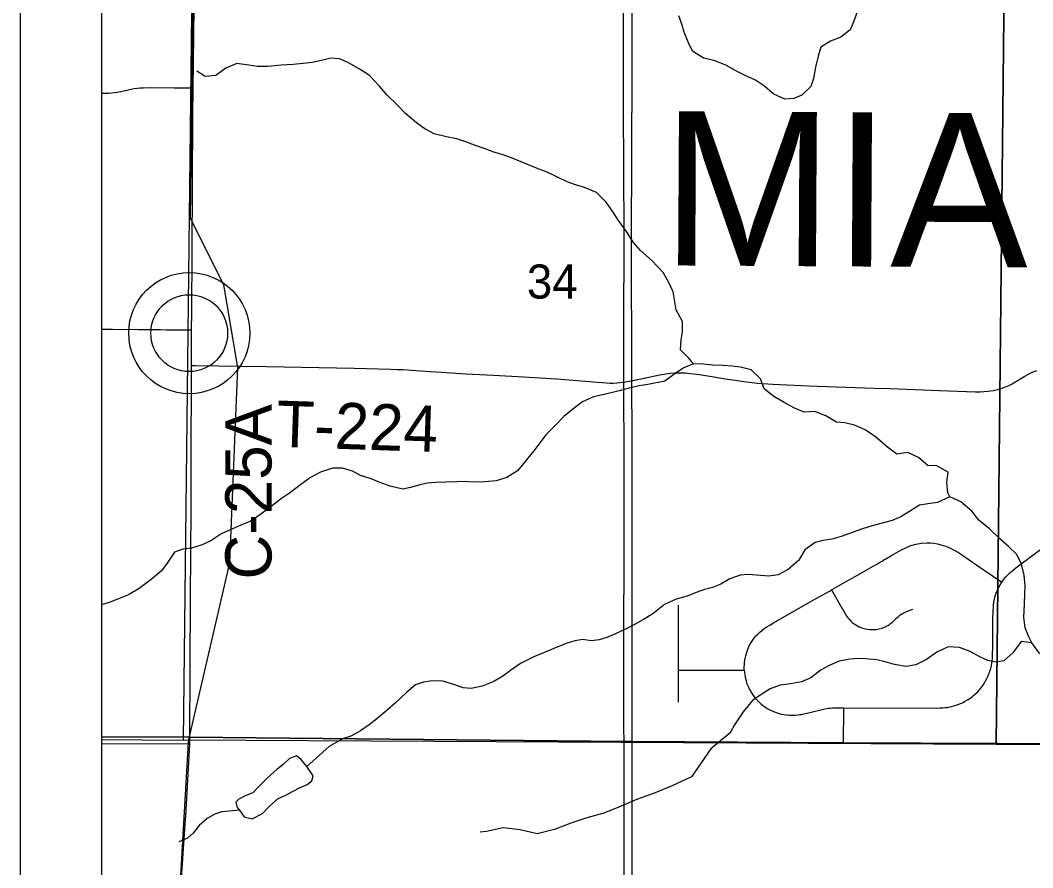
# Model space of a CAD drawing. Extents: x -38.1 to 35.9, y -2.7 to 28.5.
# Drawn here: x 8.015 to 9.259, y 17.716 to 18.757 of the extents above; entities that cross this region are included whole.
import ezdxf

# ---------------------------------------------------------------- set-up
doc = ezdxf.new("R2010")
doc.units = 0
for name, color, linetype in [('GM_X_City_Street_Text', 7, 'Continuous'), ('GM_X_Corporation', 7, 'Continuous'), ('GM_X_Corporation_Text', 7, 'Continuous'), ('GM_X_County_ROW', 7, 'Continuous'), ('GM_X_Major_River_Text', 7, 'Continuous'), ('GM_X_Minor_Lake', 7, 'Continuous'), ('GM_X_Minor_River', 7, 'Continuous'), ('GM_X_Rail_Line', 7, 'Continuous'), ('GM_X_Section', 7, 'Continuous'), ('GM_X_State_Location', 7, 'Continuous'), ('GM_X_Township', 7, 'Continuous'), ('GM_X_US_Route', 7, 'Continuous'), ('SC_Scratch10', 7, 'Continuous'), ('SH_Border', 7, 'Continuous'), ('SH_Data', 7, 'Continuous')]:
    doc.layers.add(name, color=color, linetype=linetype)

msp = doc.modelspace()

# ---------------------------------------------------------------- linework, layer by layer
at = {"layer": 'GM_X_City_Street_Text'}
for p, q in [((8.225, 18.3326), (8.2252, 18.3763)), ((8.1146, 17.8683), (8.2231, 17.868))]:
    msp.add_line(p, q, dxfattribs=at)
for points in [[(8.2272, 18.674), (8.2276, 18.704), (8.2294, 18.8765)], [(8.2252, 18.3763), (8.2253, 18.3982), (8.2257, 18.4727), (8.2268, 18.6384), (8.2272, 18.674)], [(8.1146, 18.3774), (8.128, 18.3772), (8.1597, 18.377), (8.1684, 18.3769), (8.1746, 18.3769), (8.187, 18.3767), (8.1944, 18.3766), (8.2062, 18.3765), (8.2174, 18.3764), (8.2252, 18.3763)], [(8.2231, 17.8756), (8.224, 18.0471), (8.2245, 18.157), (8.2246, 18.1724), (8.2246, 18.1898), (8.2246, 18.1954), (8.2245, 18.2077), (8.225, 18.3326)], [(8.1677, 16.8817), (8.1695, 16.9932), (8.1765, 17.1126), (8.1815, 17.1762), (8.1988, 17.4691), (8.2052, 17.587), (8.2104, 17.6664), (8.2151, 17.7391), (8.2187, 17.7863), (8.2231, 17.868), (8.2231, 17.8756)]]:
    msp.add_lwpolyline(points, dxfattribs=at)
at = {"layer": 'GM_X_Corporation'}
for points in [[(8.2224, 17.8749), (8.2723, 18.0901), (8.2822, 18.3302), (8.2647, 18.4319), (8.2238, 18.5131), (8.2346, 19.3814), (8.3741, 19.3825), (8.9096, 19.7308)], [(8.1169, 12.9308), (8.1202, 13.4509), (8.1267, 14.3761), (8.1272, 14.5808), (8.1295, 14.9033), (8.1448, 15.2944), (8.1561, 15.4105), (8.2031, 15.8872), (8.1758, 16.5559), (8.1657, 16.8852), (8.1819, 17.1843), (8.2212, 17.8697), (8.2224, 17.8749)]]:
    msp.add_lwpolyline(points, dxfattribs=at)
at = {"layer": 'GM_X_Corporation_Text'}
for points in [[(8.7566, 17.8702), (8.7564, 17.8882), (8.7566, 18.2138), (8.7564, 18.3123), (8.7563, 18.3729), (8.7565, 18.4952), (8.756, 18.6507), (8.756, 18.8701), (8.756, 18.8775), (8.756, 19.0727), (8.756, 19.2616), (8.7561, 19.3813), (8.7561, 19.3828), (8.7556, 19.4318), (8.7555, 19.4834), (8.7557, 19.6068), (8.7558, 19.7308)], [(8.7664, 17.8701), (8.7666, 18.0138), (8.7665, 18.2438), (8.7663, 18.314), (8.7659, 18.4879), (8.7665, 18.6953), (8.7665, 18.8603), (8.7664, 18.8775), (8.7659, 19.0196), (8.7659, 19.2772), (8.7659, 19.3825), (8.7659, 19.3835)], [(8.7584, 16.4935), (8.7576, 16.6966), (8.7571, 16.8386), (8.7573, 16.969), (8.7576, 17.0093), (8.7576, 17.0139), (8.7575, 17.1756), (8.7573, 17.3174), (8.7571, 17.4714), (8.7571, 17.6068), (8.7568, 17.6716), (8.7567, 17.7848), (8.7566, 17.8702)], [(8.767, 16.8813), (8.7671, 16.9689), (8.7674, 17.0079), (8.7675, 17.0138), (8.7673, 17.1755), (8.7671, 17.3173), (8.767, 17.4713), (8.767, 17.6067), (8.7666, 17.6715), (8.7665, 17.7847), (8.7664, 17.8701)]]:
    msp.add_lwpolyline(points, dxfattribs=at)
at = {"layer": 'GM_X_County_ROW'}
msp.add_line((8.2223, 18.3724), (8.2223, 18.3724), dxfattribs=at)
at = {"layer": 'GM_X_Major_River_Text'}
for p, q in [((8.8236, 17.9583), (8.8235, 18.0383)), ((8.8234, 17.919), (8.8236, 17.9583)), ((8.8236, 17.9583), (8.9042, 17.9585)), ((9.0264, 17.8684), (9.0268, 17.912))]:
    msp.add_line(p, q, dxfattribs=at)
for points in [[(8.1146, 18.6674), (8.1185, 18.6673), (8.123, 18.6674), (8.1267, 18.6677), (8.1305, 18.668), (8.1342, 18.6685), (8.1379, 18.6692), (8.1414, 18.6701), (8.1457, 18.6711), (8.1511, 18.6723), (8.1545, 18.6729), (8.1585, 18.6734), (8.1621, 18.6738), (8.1659, 18.674), (8.1759, 18.6742), (8.2038, 18.6739), (8.2181, 18.674), (8.2272, 18.674)], [(8.225, 18.3326), (8.2297, 18.3325), (8.2859, 18.3317), (8.3172, 18.3313), (8.4248, 18.3292), (8.47, 18.3282), (8.4778, 18.3279), (8.4842, 18.3276), (8.5065, 18.3262), (8.532, 18.3244), (8.5622, 18.3225), (8.5878, 18.3211), (8.6037, 18.3203), (8.6261, 18.3191), (8.674, 18.3162), (8.7239, 18.3121), (8.7299, 18.3117), (8.7346, 18.3113), (8.7396, 18.311), (8.7431, 18.3109), (8.7478, 18.3112), (8.7552, 18.3121), (8.7564, 18.3123), (8.7604, 18.3129), (8.7663, 18.314), (8.7675, 18.3143), (8.7832, 18.3175), (8.8001, 18.321), (8.8132, 18.3232), (8.8195, 18.3237), (8.8242, 18.3238), (8.828, 18.3237), (8.8319, 18.3235), (8.8379, 18.3229), (8.8421, 18.3224), (8.8492, 18.3215), (8.8669, 18.3186), (8.8809, 18.3163), (8.8901, 18.3149), (8.9036, 18.3129), (8.9207, 18.3111), (8.9392, 18.3096), (8.9662, 18.3083), (8.9739, 18.308), (8.9937, 18.3074), (9.0526, 18.3051), (9.0638, 18.3048), (9.0837, 18.3043), (9.144, 18.3021), (9.1885, 18.3005), (9.1942, 18.3005), (9.1988, 18.3007), (9.2035, 18.301), (9.2069, 18.3014), (9.2106, 18.302), (9.2175, 18.3036), (9.2244, 18.3059), (9.2287, 18.3078), (9.2334, 18.3102), (9.2388, 18.3134), (9.2491, 18.3197), (9.2536, 18.3221), (9.2571, 18.3239), (9.2636, 18.3265)], [(9.2206, 18.0666), (9.2237, 18.0706), (9.2258, 18.073), (9.228, 18.0754), (9.2307, 18.078), (9.2346, 18.0814), (9.2378, 18.0839), (9.2413, 18.0866), (9.2731, 18.1101), (9.31, 18.1378), (9.3336, 18.1555), (9.3401, 18.1603), (9.3455, 18.1645)], [(9.0115, 18.057), (9.0286, 18.0667), (9.0405, 18.0735), (9.054, 18.0811), (9.0626, 18.086), (9.0679, 18.0891), (9.0715, 18.0914), (9.0737, 18.0924), (9.0757, 18.0937), (9.0783, 18.0952), (9.0831, 18.098), (9.0857, 18.0996), (9.0879, 18.1008), (9.0936, 18.1042), (9.0982, 18.1066), (9.101, 18.108), (9.1044, 18.1096), (9.1051, 18.1099), (9.1091, 18.1114), (9.1107, 18.1119), (9.1152, 18.1131), (9.1221, 18.1143), (9.1286, 18.1147), (9.133, 18.1146), (9.1372, 18.1143), (9.1417, 18.1135), (9.1458, 18.1125), (9.1506, 18.1111), (9.1529, 18.1103), (9.1577, 18.1082), (9.1606, 18.1067), (9.1638, 18.1049), (9.1676, 18.1027), (9.1713, 18.1003), (9.1902, 18.0874), (9.2206, 18.0666)], [(9.0268, 17.912), (9.1399, 17.9117), (9.1447, 17.9119), (9.1482, 17.9121), (9.151, 17.9123), (9.1536, 17.9126), (9.155, 17.9128), (9.1568, 17.9132), (9.1594, 17.9138), (9.1615, 17.9144), (9.1647, 17.9154), (9.1678, 17.9164), (9.1712, 17.9177), (9.1733, 17.9187), (9.175, 17.9197), (9.1792, 17.9221), (9.1816, 17.9237), (9.1846, 17.926), (9.1869, 17.9279), (9.1895, 17.9303), (9.1911, 17.9318), (9.1928, 17.9339), (9.195, 17.9364), (9.1973, 17.9396), (9.1989, 17.942), (9.2008, 17.9452), (9.2023, 17.948), (9.2038, 17.9513), (9.2048, 17.9538), (9.206, 17.9569), (9.2071, 17.9603), (9.208, 17.9639), (9.2085, 17.9665), (9.2089, 17.9695), (9.2092, 17.9725), (9.2094, 17.9767), (9.2098, 17.988), (9.2099, 18.0197), (9.2102, 18.0309), (9.2105, 18.0365), (9.2107, 18.0395), (9.2109, 18.0407), (9.2111, 18.0427), (9.2113, 18.0439), (9.2116, 18.0456), (9.2122, 18.0477), (9.2127, 18.0496), (9.2134, 18.0516), (9.2143, 18.0541), (9.2154, 18.0567), (9.2168, 18.0596), (9.2186, 18.0631), (9.2206, 18.0666)], [(8.9042, 17.9585), (8.9043, 17.962), (8.9044, 17.9658), (8.9045, 17.9673), (8.905, 17.9709), (8.906, 17.9758), (8.9077, 17.9817), (8.9094, 17.9862), (8.9112, 17.99), (8.9135, 17.9937), (8.9151, 17.996), (8.9178, 17.9996), (8.9186, 18.0005), (8.9208, 18.0027), (8.9228, 18.0046), (8.9263, 18.0075), (8.9289, 18.0095), (8.9312, 18.0111), (8.9356, 18.0138), (8.9401, 18.0163), (8.9823, 18.0405), (8.9908, 18.0454), (9.0097, 18.056), (9.0115, 18.057)], [(9.0115, 18.057), (9.0249, 18.0333), (9.0271, 18.0298), (9.0305, 18.0243), (9.0323, 18.0219), (9.0334, 18.0205), (9.0352, 18.0187), (9.037, 18.017), (9.0392, 18.0153), (9.0413, 18.0139), (9.0435, 18.0127), (9.0454, 18.0117), (9.0481, 18.0106), (9.05, 18.0099), (9.0531, 18.0091), (9.0547, 18.0087), (9.0584, 18.0083), (9.06, 18.0081), (9.0622, 18.0081), (9.0636, 18.0081), (9.0658, 18.0083), (9.0672, 18.0084), (9.0702, 18.009), (9.0738, 18.01), (9.0755, 18.0107), (9.0777, 18.0116), (9.0788, 18.0122), (9.0805, 18.0131), (9.0827, 18.0146), (9.0845, 18.0159), (9.0868, 18.0179), (9.0918, 18.0226), (9.0936, 18.0243), (9.096, 18.0262), (9.0978, 18.0274), (9.0991, 18.0281), (9.1004, 18.0288), (9.1019, 18.0295), (9.1026, 18.0298), (9.1056, 18.0311), (9.1112, 18.0334)], [(8.9042, 17.9585), (8.9044, 17.9564), (8.9048, 17.9529), (8.9054, 17.9497), (8.906, 17.9472), (8.9065, 17.9449), (8.9076, 17.9416), (8.9086, 17.9391), (8.9097, 17.9366), (8.9108, 17.9345), (8.9122, 17.932), (8.914, 17.9293), (8.9153, 17.9273), (8.9185, 17.9233), (8.9204, 17.9211), (8.923, 17.9187), (8.9252, 17.9167), (8.9283, 17.9143), (8.9304, 17.9127), (8.9325, 17.9113), (8.9364, 17.9092), (8.9401, 17.9075), (8.9434, 17.9062), (8.9473, 17.905), (8.9497, 17.9044), (8.9532, 17.9037), (8.9558, 17.9034), (8.9595, 17.9031), (8.9616, 17.903), (8.9654, 17.903), (8.9674, 17.9031), (8.9704, 17.9034), (8.9725, 17.9037), (8.9746, 17.904), (8.9776, 17.9046), (8.9848, 17.9063), (9.0016, 17.9105), (9.0052, 17.9113), (9.0077, 17.9116), (9.0099, 17.9118), (9.0126, 17.9119), (9.0165, 17.9119), (9.0268, 17.912)]]:
    msp.add_lwpolyline(points, dxfattribs=at)
at = {"layer": 'GM_X_Section'}
for points in [[(9.0433, 18.7683), (9.039, 18.7558), (9.0343, 18.7449), (9.0228, 18.7359), (9.0102, 18.7311), (8.9984, 18.7237), (8.9952, 18.7127), (8.992, 18.6994), (8.9892, 18.6854), (8.986, 18.6756), (8.9749, 18.6647), (8.965, 18.6606), (8.954, 18.66), (8.9404, 18.6659), (8.928, 18.6767), (8.9179, 18.6832), (8.9054, 18.6891), (8.8949, 18.6942), (8.8824, 18.7011), (8.8674, 18.7074), (8.8541, 18.7102), (8.8406, 18.7188), (8.8358, 18.7291), (8.8306, 18.7424), (8.8277, 18.752), (8.8237, 18.7623)], [(8.842, 18.3347), (8.8356, 18.342), (8.8259, 18.352), (8.8268, 18.3641), (8.8284, 18.374), (8.8282, 18.3869), (8.8204, 18.401), (8.819, 18.4109), (8.8169, 18.4231), (8.8121, 18.4338), (8.8046, 18.4468), (8.7912, 18.4614), (8.7769, 18.4741), (8.7683, 18.4837), (8.7594, 18.4971), (8.7497, 18.5109), (8.743, 18.5209), (8.7344, 18.5335), (8.7228, 18.5451), (8.7081, 18.5513), (8.6971, 18.5545), (8.6865, 18.5584), (8.6749, 18.5639), (8.662, 18.5701), (8.6488, 18.5752), (8.6349, 18.5807), (8.6183, 18.5877), (8.6069, 18.5921), (8.5964, 18.5948), (8.5858, 18.5988), (8.5726, 18.6035), (8.5609, 18.6078), (8.551, 18.611), (8.5382, 18.6138), (8.5231, 18.6174), (8.5118, 18.6236), (8.5016, 18.6306), (8.4881, 18.6421), (8.4776, 18.6529), (8.4652, 18.6652), (8.4559, 18.676), (8.4439, 18.689), (8.4322, 18.6964), (8.4187, 18.7041), (8.4074, 18.7096), (8.3964, 18.7101), (8.3865, 18.708), (8.3732, 18.7051), (8.3622, 18.7037), (8.35, 18.7023), (8.3352, 18.7017), (8.3189, 18.7), (8.306, 18.7002), (8.2954, 18.7018), (8.2806, 18.7035), (8.2673, 18.698), (8.2551, 18.689), (8.2418, 18.6877), (8.2316, 18.6943)], [(9.157, 18.1713), (9.1544, 18.1763), (9.1531, 18.1892), (9.1547, 18.2017), (9.14, 18.2099), (9.1302, 18.2092), (9.1185, 18.2196), (9.1053, 18.2259), (9.0917, 18.2237), (9.0804, 18.2322), (9.0654, 18.245), (9.053, 18.2538), (9.0398, 18.2593), (9.0277, 18.2621), (9.0178, 18.263), (9.0046, 18.2708), (8.991, 18.2763), (8.9778, 18.2753), (8.9653, 18.2807), (8.9533, 18.287), (8.9405, 18.2947), (8.9288, 18.304), (8.9244, 18.3162), (8.9128, 18.3273), (8.8996, 18.3305), (8.8893, 18.3318), (8.8783, 18.3327), (8.8655, 18.3332), (8.8541, 18.3341), (8.842, 18.3347), (8.8301, 18.3299), (8.8194, 18.3228), (8.8068, 18.3135), (8.7859, 18.3095), (8.7753, 18.3078), (8.7627, 18.3049), (8.7505, 18.3016), (8.7407, 18.2991), (8.7285, 18.2962), (8.719, 18.294), (8.7056, 18.2881), (8.6957, 18.2806), (8.6827, 18.2698), (8.6731, 18.26), (8.6604, 18.2476), (8.6531, 18.2375), (8.6457, 18.2277), (8.6257, 18.2032), (8.6127, 18.195), (8.5994, 18.191), (8.5854, 18.1897), (8.571, 18.1895), (8.5607, 18.19), (8.5509, 18.1897), (8.5376, 18.1895), (8.5254, 18.1889), (8.5148, 18.1879), (8.5045, 18.1857), (8.4943, 18.1828), (8.4848, 18.1806), (8.4693, 18.1846), (8.4557, 18.1893), (8.4458, 18.1933), (8.4326, 18.1976), (8.4228, 18.203), (8.4107, 18.2066), (8.3982, 18.2064), (8.3834, 18.2016), (8.3712, 18.1949), (8.3593, 18.1863), (8.3455, 18.1759), (8.3356, 18.1691), (8.321, 18.1576), (8.3092, 18.149), (8.2973, 18.1411), (8.2866, 18.1367), (8.2737, 18.1312), (8.2622, 18.1264), (8.2489, 18.1174), (8.2382, 18.1122), (8.2249, 18.1082), (8.2146, 18.1068), (8.2043, 18.1035), (8.1958, 18.0911), (8.1881, 18.0805), (8.1755, 18.0697), (8.1609, 18.0585), (8.1476, 18.051), (8.1335, 18.0451), (8.1239, 18.0414), (8.1146, 18.0386)], [(9.2576, 17.9919), (9.2535, 18.0003), (9.2495, 18.0103), (9.2478, 18.0236), (9.2487, 18.0395), (9.2492, 18.052), (9.2494, 18.0619), (9.2484, 18.0752), (9.2451, 18.0886), (9.2392, 18.1004), (9.2291, 18.1104), (9.2186, 18.1193), (9.2055, 18.132), (9.1927, 18.1427), (9.1841, 18.1535), (9.1702, 18.1651), (9.157, 18.1713), (9.1418, 18.1643), (9.13, 18.1625), (9.1197, 18.1611), (9.1098, 18.1548), (9.0968, 18.1466), (9.0861, 18.1422), (9.0721, 18.1385), (9.0614, 18.1356), (9.0496, 18.132), (9.0382, 18.1279), (9.0233, 18.1224), (9.0119, 18.1191), (9.0009, 18.1178), (8.9914, 18.1152), (8.9788, 18.1062), (8.9714, 18.0934), (8.9584, 18.0822), (8.9458, 18.0755), (8.9344, 18.0737), (8.9192, 18.0751), (8.9086, 18.076), (8.8991, 18.0749), (8.8865, 18.0705), (8.8755, 18.0642), (8.8652, 18.0598), (8.8553, 18.0576), (8.845, 18.0536), (8.8343, 18.0491), (8.8206, 18.0455), (8.8061, 18.0389), (8.792, 18.0276), (8.7805, 18.0206), (8.7695, 18.0146), (8.7599, 18.0094), (8.7462, 18.0028), (8.7355, 17.9983), (8.726, 17.9954), (8.7161, 17.9944), (8.7059, 17.996), (8.696, 17.9943), (8.6854, 17.9913), (8.6701, 17.9851), (8.6598, 17.9806), (8.6457, 17.9747), (8.6293, 17.9666), (8.6171, 17.958), (8.6075, 17.9509), (8.5964, 17.9446), (8.5823, 17.9387), (8.5686, 17.9358), (8.5588, 17.9367), (8.5475, 17.9406), (8.5339, 17.945), (8.5202, 17.9451), (8.5103, 17.9437), (8.5004, 17.9404), (8.4893, 17.9307), (8.4759, 17.9183), (8.4656, 17.9093), (8.4529, 17.8985), (8.4433, 17.891), (8.4326, 17.8839), (8.4208, 17.8772), (8.4105, 17.8739), (8.3943, 17.8645)], [(9.2673, 17.9785), (9.2576, 17.9919), (9.2447, 17.9936), (9.2343, 17.9797), (9.2232, 17.9699), (9.2137, 17.9682), (9.2035, 17.9702), (9.1937, 17.9749), (9.182, 17.9811), (9.1688, 17.9862), (9.1548, 17.9871), (9.1407, 17.9805), (9.1281, 17.9715), (9.1151, 17.9648), (9.1033, 17.9627), (9.0889, 17.9651), (9.0772, 17.9687), (9.067, 17.9711), (9.0534, 17.9724), (9.0439, 17.9725), (9.034, 17.9719), (9.0207, 17.9694), (9.0085, 17.9642), (8.9986, 17.9587), (8.986, 17.9489), (8.9745, 17.9438), (8.9612, 17.9416), (8.9483, 17.9399), (8.9361, 17.9355), (8.9239, 17.9277), (8.9143, 17.921), (8.9028, 17.907), (8.8924, 17.8912), (8.8869, 17.8814), (8.863, 17.8617)], [(8.3666, 17.8401), (8.3943, 17.8645)], [(8.863, 17.8617), (8.8394, 17.8272), (8.8166, 17.8166), (8.7949, 17.8075), (8.7709, 17.7991), (8.7511, 17.7904), (8.7318, 17.7828), (8.7108, 17.7771), (8.6911, 17.7702), (8.6713, 17.7626), (8.6496, 17.7573), (8.6291, 17.7623), (8.6082, 17.7645), (8.5876, 17.76), (8.5796, 17.7592)], [(8.2841, 17.7864), (8.2623, 17.7843), (8.2539, 17.7814), (8.2443, 17.7762), (8.2343, 17.7673), (8.2273, 17.7579), (8.2203, 17.7519), (8.2093, 17.7475)]]:
    msp.add_lwpolyline(points, dxfattribs=at)
at = {"layer": 'GM_X_State_Location'}
for radius in [0.0744, 0.0472]:
    msp.add_circle((8.2223, 18.3724), radius, dxfattribs=at)
at = {"layer": 'GM_X_US_Route'}
for points in [[(14.9146, 19.7308), (8.1146, 19.7308), (8.1146, 17.8763), (8.2228, 17.8761), (8.7564, 17.8708), (8.7662, 17.8706), (9.0262, 17.8689), (9.5019, 17.8671), (9.8985, 17.8644), (9.9118, 17.8643), (10.4152, 17.8803), (10.3361, 17.7853), (10.2437, 17.6904)], [(11.2375, 19.7308), (8.1146, 19.7308), (8.1146, 17.8763), (8.2228, 17.8761), (8.7564, 17.8708), (8.7662, 17.8706), (9.0262, 17.8689), (9.5019, 17.8671), (9.8985, 17.8644), (9.9118, 17.8643), (10.4152, 17.8803)], [(10.2437, 17.6904), (10.3361, 17.7853), (10.4152, 17.8803), (9.9118, 17.8643), (9.8985, 17.8644), (9.5019, 17.8671), (9.0262, 17.8689), (8.7662, 17.8706), (8.7564, 17.8708), (8.2228, 17.8761), (8.1146, 17.8763), (8.1146, 12.9308)], [(10.2437, 17.6904), (10.3361, 17.7853), (10.4152, 17.8803), (9.9118, 17.8643), (9.8985, 17.8644), (9.5019, 17.8671), (9.0262, 17.8689), (8.7662, 17.8706), (8.7564, 17.8708), (8.2228, 17.8761), (8.1146, 17.8763), (8.1146, 12.9308)]]:
    msp.add_lwpolyline(points, dxfattribs=at)
for points in [[(8.1146, 18.8757), (8.1146, 17.873), (8.2154, 17.8724), (8.2269, 18.8735)], [(8.2269, 18.8735), (9.2246, 18.878), (9.2136, 17.8669), (8.2154, 17.8724)], [(9.2246, 18.878), (10.2384, 18.8764), (10.2156, 17.8613), (9.2136, 17.8669)]]:
    msp.add_lwpolyline(points, close=True, dxfattribs=at)
at = {"layer": 'SC_Scratch10'}
for points in [[(8.3666, 17.8401), (8.3595, 17.849), (8.3539, 17.8529), (8.3455, 17.8496), (8.3378, 17.8425), (8.3305, 17.8365), (8.3181, 17.8257), (8.3077, 17.8156), (8.3004, 17.8078), (8.2912, 17.8041), (8.2832, 17.7997), (8.2797, 17.7963), (8.2811, 17.7895), (8.2841, 17.7864)], [(8.2841, 17.7864), (8.2897, 17.778), (8.2995, 17.7755), (8.3125, 17.7821), (8.321, 17.7911), (8.3314, 17.8008), (8.3402, 17.8045), (8.3498, 17.8096), (8.3578, 17.8137), (8.367, 17.8177), (8.3731, 17.8222), (8.3744, 17.8286), (8.3666, 17.8401)]]:
    msp.add_lwpolyline(points, dxfattribs=at)
at = {"layer": 'SH_Border'}
msp.add_line((8.1146, 19.7308), (8.1146, 12.9308), dxfattribs=at)
at = {"layer": 'SH_Data'}
msp.add_line((8.0146, 19.8308), (8.0146, 12.8308), dxfattribs=at)

# ---------------------------------------------------------------- texts
at = {"layer": 'GM_X_Minor_Lake'}
msp.add_text('T-224', height=0.05682, rotation=358.0729, dxfattribs=at).set_placement((8.3286, 18.2329))
at = {"layer": 'GM_X_Minor_River'}
msp.add_text('34', height=0.04186, rotation=0, dxfattribs=at).set_placement((8.6372, 18.4149))
at = {"layer": 'GM_X_Rail_Line'}
msp.add_text('MIAMI COUNTY', height=0.189394, rotation=359.6735, dxfattribs=at).set_placement((8.8022, 18.4557))
at = {"layer": 'GM_X_Township'}
msp.add_text('C-25A', height=0.05682, rotation=90, dxfattribs=at).set_placement((8.3234, 18.0698))

doc.saveas('drawing.dxf')
